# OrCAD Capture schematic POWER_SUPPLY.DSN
size A
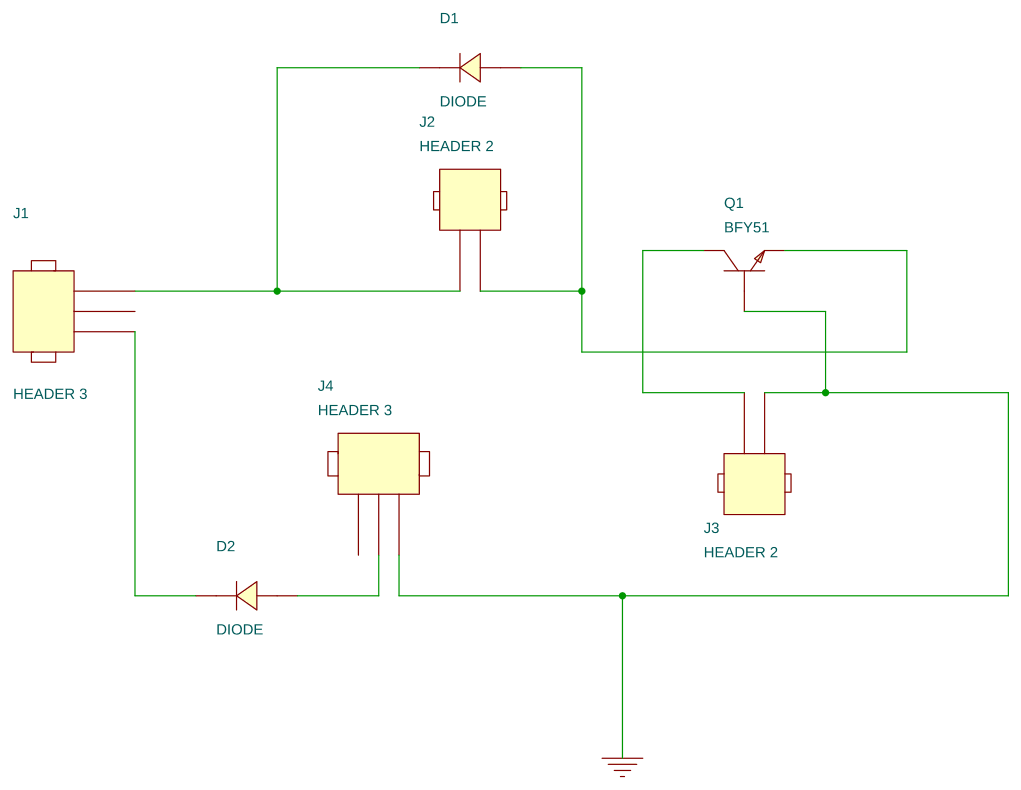
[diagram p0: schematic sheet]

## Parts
D1  DIODE  [GU-led5mm]
D2  DIODE  [GU-led5mm]
J1  HEADER 3  [GU-TERMINAL3-200]
J2  HEADER 2  [GU-TERMINAL2-200]
J3  HEADER 2  [GU-TERMINAL2-200]
J4  HEADER 3  [GU-JUMPER3]
Q1  BFY51  [GU-MOLEX3]

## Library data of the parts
D1 D2 = DIODE
J1 J4 = HEADER_3
J2 J3 = HEADER_2
Q1 = BFY51

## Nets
GND_POWER: J3.2 J4.1 Q1.2(BASE)
N00225: D1.2(K) J1.1 J2.2
N00237: D1.1(A) J2.1 Q1.1(EMITTER)
N00241: J3.1 Q1.3(COLLECTOR)
N00263: D2.2(K) J1.3
N00753: D2.1(A) J4.2

Not connected (* = marked no-connect by the designer): J1 2; J4 3
